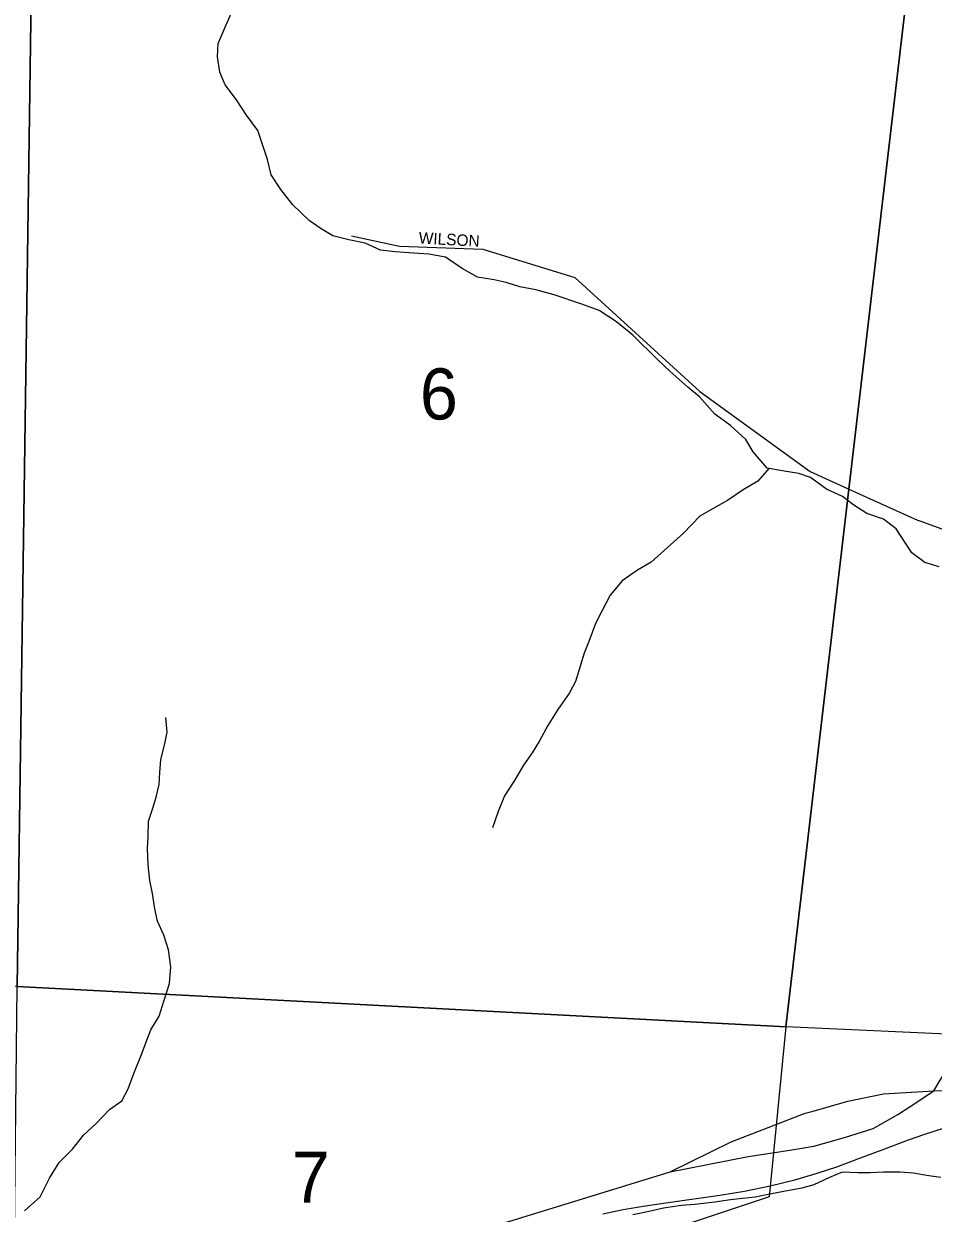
# Model space of a CAD drawing. Extents: x 1624196 to 2029251, y 146837 to 440034.
# Drawn here: x 1851645 to 1855581, y 275807 to 280955 of the extents above; entities that cross this region are included whole.
import ezdxf

# ---------------------------------------------------------------- set-up
doc = ezdxf.new("R2010")
doc.units = 0
for name, color, linetype in [('GM_X_City_Street', 7, 'Continuous'), ('GM_X_City_Street_Text', 7, 'Continuous'), ('GM_X_Major_River', 7, 'Continuous'), ('GM_X_Minor_River', 7, 'Continuous'), ('GM_X_Rail_Line', 7, 'Continuous'), ('GM_X_Section', 7, 'Continuous'), ('GM_X_Section_Text', 7, 'Continuous'), ('GM_X_State_Route', 7, 'Continuous'), ('GM_X_US_Route', 7, 'Continuous')]:
    doc.layers.add(name, color=color, linetype=linetype)

msp = doc.modelspace()

# ---------------------------------------------------------------- linework, layer by layer
at = {"layer": 'GM_X_City_Street'}
for points in [[(1853062.9, 280037), (1853270.9, 279992.7), (1853631.5, 279978.9), (1854029, 279856.3), (1854571.1, 279363.2), (1855048.6, 279017.2), (1855260, 278920.7), (1855512.5, 278807), (1855518.1, 278804.9)], [(1855518.1, 278804.9), (1856127.6, 278584.2), (1856317.2, 278532.3), (1856482.9, 278504.3), (1856517, 278500.3)]]:
    msp.add_lwpolyline(points, dxfattribs=at)
at = {"layer": 'GM_X_Major_River'}
msp.add_lwpolyline([(1855614.1, 275961.3), (1855562.1, 275969.2), (1855494.1, 275981), (1855438.1, 275984.9), (1855366.2, 275984.7), (1855308.2, 275982.6), (1855256.2, 275982.5), (1855186.2, 275984.3), (1855132.3, 275962.1), (1855064.4, 275929.9), (1855012.5, 275915.8), (1854934.6, 275901.6), (1854880.6, 275891.5), (1854810.7, 275877.3), (1854754.7, 275871.1), (1854702.8, 275865), (1854634.8, 275854.8), (1854548.9, 275844.6), (1854490.9, 275840.5), (1854413, 275828.3), (1854351.1, 275814.1), (1854281.1, 275799.9)], dxfattribs=at)
at = {"layer": 'GM_X_Minor_River'}
for points in [[(1855606, 278605.2), (1855544, 278623.1), (1855488, 278665), (1855419.8, 278769), (1855365.7, 278810.9), (1855293.7, 278834.8), (1855237.6, 278870.7), (1855187.6, 278908.7), (1855119.5, 278940.5), (1855049.4, 278990.5), (1854999.4, 279008.4), (1854935.4, 279018.2), (1854861.4, 279032.1), (1854801.3, 279102), (1854769.2, 279156), (1854703.1, 279216), (1854635, 279265.9), (1854568.9, 279339.9), (1854518.8, 279381.8), (1854440.7, 279451.7), (1854388.6, 279499.7), (1854280.4, 279607.6), (1854210.3, 279665.5), (1854134.2, 279713.4), (1854060.2, 279741.3), (1853940.2, 279781), (1853860.2, 279802.9), (1853792.2, 279816.8), (1853732.2, 279834.6), (1853680.2, 279846.5), (1853608.2, 279858.4), (1853542.1, 279896.3), (1853470, 279944.2), (1853398, 279958), (1853332.1, 279961.9), (1853252.1, 279967.7), (1853188.1, 279975.6), (1853122.1, 280005.5), (1853052.1, 280019.3), (1852982.1, 280037.2), (1852932, 280067.1), (1852880, 280103.1), (1852809.8, 280171), (1852757.7, 280237), (1852715.6, 280301), (1852699.4, 280367), (1852675.3, 280441.1), (1852657.2, 280493.1), (1852609, 280559.1), (1852564.9, 280625.1), (1852516.8, 280691.1), (1852492.7, 280745.1), (1852482.5, 280811.2), (1852486.4, 280869.3), (1852520.2, 280949.5), (1852550, 281015.6)], [(1854869.1, 279030.7), (1854821.6, 278975.9), (1854757.7, 278937.7), (1854689.8, 278891.5), (1854637.9, 278863.3), (1854570.1, 278823.1), (1854500.3, 278750.8), (1854430.4, 278688.6), (1854360.6, 278624.3), (1854300.7, 278590.1), (1854234.9, 278543.9), (1854183, 278481.7), (1854147.2, 278415.5), (1854119.3, 278359.3), (1854089.5, 278281.2), (1854069.7, 278231), (1854053.8, 278178.9), (1854032, 278108.8), (1854006.1, 278058.6), (1853956.3, 277986.4), (1853912.5, 277918.2), (1853876.6, 277852), (1853844.8, 277799.9), (1853806.9, 277745.7), (1853765.1, 277675.5), (1853725.2, 277613.3), (1853697.4, 277545.1), (1853673.6, 277475)], [(1851648.4, 275817.8), (1851716.2, 275878), (1851756, 275958.3), (1851797.8, 276026.5), (1851855.7, 276084.7), (1851903.5, 276144.9), (1851957.4, 276195.1), (1852015.2, 276255.3), (1852069.1, 276293.5), (1852097, 276345.6), (1852120.8, 276411.8), (1852154.6, 276494), (1852172.5, 276544.1), (1852194.3, 276600.2), (1852230.2, 276660.4), (1852252, 276728.6), (1852275.8, 276800.7), (1852281.7, 276872.8), (1852271.5, 276946.9), (1852251.3, 277011), (1852223.2, 277071), (1852211.1, 277125), (1852201, 277191.1), (1852190.8, 277247.2), (1852182.7, 277315.3), (1852180.5, 277385.4), (1852182.4, 277437.5), (1852184.3, 277503.5), (1852202.1, 277555.7), (1852218, 277607.8), (1852229.9, 277661.9), (1852233.8, 277714), (1852237.6, 277770.1), (1852255.5, 277838.2), (1852265.3, 277888.3), (1852259.2, 277952.4)]]:
    msp.add_lwpolyline(points, dxfattribs=at)
at = {"layer": 'GM_X_Rail_Line'}
for points in [[(1855254.4, 276041.8), (1855359.1, 276081.3), (1855473.6, 276124.8), (1855543.7, 276149.8), (1855625.1, 276175.6)], [(1854150.9, 275804), (1854238.8, 275823.3), (1854325, 275837.8), (1854433, 275853.2), (1854657.1, 275884.6), (1854763.5, 275902.3), (1854875.5, 275925.7), (1854981.9, 275951.5), (1855074.6, 275979.7), (1855167.3, 276009.5), (1855254.4, 276041.8)]]:
    msp.add_lwpolyline(points, dxfattribs=at)
at = {"layer": 'GM_X_Section'}
for points in [[(1846841.1, 282183.3), (1851691, 282089.9), (1851615.4, 276787.9), (1846488.4, 277052.7)], [(1851691, 282089.9), (1855574.9, 282007.2), (1854942.8, 276613.9), (1851615.4, 276787.9)], [(1855574.9, 282007.2), (1856638.9, 282002.1), (1862193.5, 281747.1), (1861882.7, 276297.8), (1854942.8, 276613.9)], [(1854942.8, 276613.9), (1854871.2, 275878.2), (1851593.7, 274787.9), (1851615.4, 276787.9)]]:
    msp.add_lwpolyline(points, close=True, dxfattribs=at)
at = {"layer": 'GM_X_State_Route'}
for points in [[(1855480.6, 276268.9), (1855583.9, 276336.2), (1855614.7, 276389.8), (1855632.7, 276422.6), (1855641.8, 276436.1), (1855654.2, 276448.6), (1855675.7, 276455.4), (1855693.8, 276453.1), (1855758.2, 276447.6)], [(1854442.6, 275986.9), (1854779.6, 276052.2), (1854960.1, 276080.5), (1855064.5, 276097.9), (1855197.1, 276134.9), (1855321.3, 276173.3), (1855427, 276234), (1855480.6, 276268.9)]]:
    msp.add_lwpolyline(points, dxfattribs=at)
at = {"layer": 'GM_X_US_Route'}
for points in [[(1855060.6, 276249.1), (1855211, 276291.8), (1855365.5, 276323.1), (1855583.9, 276336.2), (1855836.5, 276341.5), (1856067.3, 276341.5), (1856205.3, 276343.3), (1856302.3, 276333.2), (1856394.3, 276320.3), (1856448, 276311.8)], [(1854442.6, 275986.9), (1854705.6, 276116.4), (1855027.2, 276239.6), (1855060.6, 276249.1)], [(1853507.4, 275724), (1853743.6, 275771.8), (1854442.6, 275986.9)]]:
    msp.add_lwpolyline(points, dxfattribs=at)

# ---------------------------------------------------------------- texts
at = {"layer": 'GM_X_City_Street_Text'}
msp.add_text('WILSON', height=50, rotation=356.8197, dxfattribs=at).set_placement((1853352.9, 280003.8))
at = {"layer": 'GM_X_Section_Text'}
for s, p in [('6', (1853359, 279242.3)), ('7', (1852804.6, 275852.7))]:
    msp.add_text(s, height=221, rotation=0, dxfattribs=at).set_placement(p)

doc.saveas('drawing.dxf')
